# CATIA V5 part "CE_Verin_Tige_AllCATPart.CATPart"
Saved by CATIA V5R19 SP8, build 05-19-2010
Part number: CE8_Verin_Tige_AllCATPart
Bounding box of the stored display mesh (mm): x -5.555 to 7, y 273.354 to 541.186, z 0.473 to 75.916
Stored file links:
  D:\Documents\1_Travail\1 - ac-limoges.fr\ac-limoges.fr\Emmanuel Maynard - STI2D_Turgot\2 -2I2D\1_SEQUENCE_ Tapis_de_course\3- Spécificités\Spé_ITEC\3-Pente\Tapis_TC520B_Pente\CE_Verin_Tige_AllCATPart.CATPart
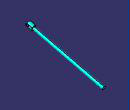
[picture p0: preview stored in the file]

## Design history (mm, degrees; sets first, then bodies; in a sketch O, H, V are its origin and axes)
AxisSystem1: origin (0, 0, 0), X (1, 0, 0), Y (0, 1, 0), Z (0, 0, 1)
Body1 (main body)
Body2 "TIGE_ST_250F1VD10.1\\MANIFOLD_SOLID_BREP #15796"
  Solid1: solid without history
Body3 "Chappe_verin.2\\Corps principal"
  Solid2 "Solide.1": solid without history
